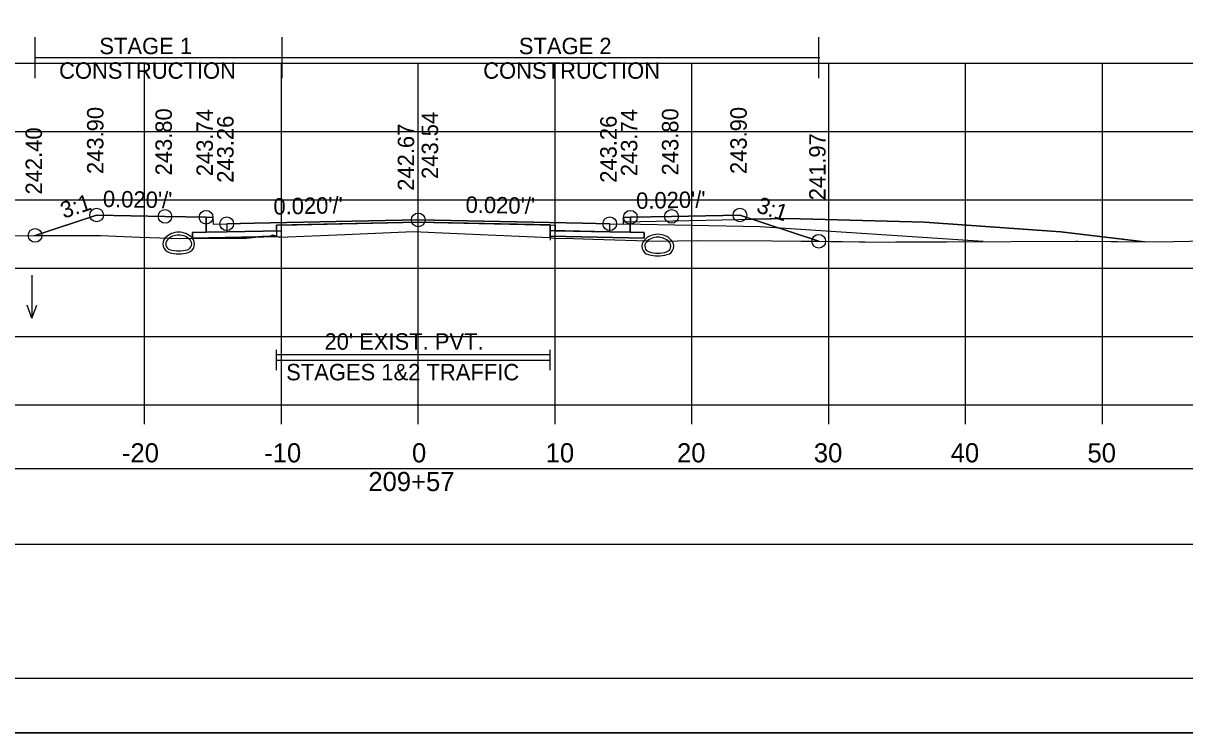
# Model space of a CAD drawing. Extents: x 1369627 to 1374022, y 380035 to 398173.
# Drawn here: x 1372069.7 to 1372154.6, y 381958.8 to 382010.7 of the extents above; entities that cross this region are included whole.
import ezdxf

# ---------------------------------------------------------------- set-up
doc = ezdxf.new("R2010")
doc.units = 0
for name, color, linetype in [('Default', 7, 'Continuous'), ('R_Alt Surface', 7, 'Continuous'), ('R_Axis', 7, 'Continuous'), ('R_Axis Annot', 7, 'Continuous'), ('R_Border', 7, 'Continuous'), ('R_Drive', 7, 'Continuous'), ('R_Exist Surface', 7, 'Continuous'), ('R_Fin Surface', 7, 'Continuous'), ('R_Grid', 7, 'Continuous'), ('R_MOT', 7, 'Continuous'), ('R_No Plot', 7, 'Continuous'), ('R_Water Annot', 7, 'Continuous'), ('R_Xsect Elev', 7, 'Continuous'), ('R_Xsect Slope', 7, 'Continuous'), ('T_Vehicle Path Lt Minor', 7, 'Continuous'), ('T_Vehicle Path Rt', 7, 'Continuous')]:
    doc.layers.add(name, color=color, linetype=linetype)

msp = doc.modelspace()

# ---------------------------------------------------------------- linework, layer by layer
at = {"layer": 'Default'}
for p, q in [((1372088.17, 381985.336), (1372088.17, 381986.836)), ((1372108.17, 381985.336), (1372108.17, 381986.836)), ((1372088.17, 381986.086), (1372108.17, 381986.086))]:
    msp.add_line(p, q, dxfattribs=at)
for points in [[(1372083.02, 381996.536), (1372083.52, 381996.536), (1372083.53, 381996.036), (1372084.53, 381996.056), (1372084.53, 381995.469), (1372083.03, 381995.439)], [(1372113.53, 381996.036), (1372113.54, 381996.536), (1372114.04, 381996.536), (1372114.03, 381995.439), (1372112.53, 381995.469), (1372112.53, 381996.056)], [(1371948.53, 381972.606), (1372248.53, 381972.606), (1372248.53, 381978.128), (1371948.53, 381978.128)]]:
    msp.add_lwpolyline(points, close=True, dxfattribs=at)
at = {"layer": 'R_Alt Surface'}
msp.add_lwpolyline([(1372083.03, 381996.537), (1372083.03, 381995.439), (1372084.53, 381995.469), (1372088.17, 381995.542), (1372088.17, 381995.959), (1372098.53, 381996.166), (1372108.17, 381995.973), (1372108.17, 381995.556), (1372112.53, 381995.469), (1372114.03, 381995.439), (1372114.031, 381996.537)], dxfattribs=at)
for points in [[(1372082.03, 381995.419), (1372083.03, 381995.439), (1372084.53, 381995.469), (1372088.17, 381995.542), (1372088.17, 381995.125), (1372082.03, 381995.003)], [(1372115.03, 381995.419), (1372114.03, 381995.439), (1372112.53, 381995.469), (1372108.17, 381995.556), (1372108.17, 381995.14), (1372115.03, 381995.003)]]:
    msp.add_lwpolyline(points, close=True, dxfattribs=at)
at = {"layer": 'R_Axis'}
for p, q in [((1371948.53, 381982.801), (1372248.53, 381982.801)), ((1372078.53, 381981.401), (1372078.53, 381982.801)), ((1372088.53, 381981.401), (1372088.53, 381982.801)), ((1372098.53, 381981.401), (1372098.53, 381982.801)), ((1372108.53, 381981.401), (1372108.53, 381982.801)), ((1372118.53, 381981.401), (1372118.53, 381982.801)), ((1372128.53, 381981.401), (1372128.53, 381982.801)), ((1372138.53, 381981.401), (1372138.53, 381982.801)), ((1372148.53, 381981.401), (1372148.53, 381982.801))]:
    msp.add_line(p, q, dxfattribs=at)
at = {"layer": 'R_Border'}
msp.add_line((1372256.71, 381962.801), (1371940.53, 381962.801), dxfattribs=at)
at = {"layer": 'R_Drive'}
for points in [[(1372113.53, 381996.036), (1372113.533, 381996.206), (1372125.531, 381996.446)], [(1372125.531, 381996.446), (1372135.527, 381996.186), (1372145.502, 381995.467), (1372151.605, 381994.744)]]:
    msp.add_lwpolyline(points, dxfattribs=at)
for centre, radius, start, end in [((1372081.02, 381994.088), 1.354, 43.64848, 136.35152), ((1372081.02, 381994.088), 1.146, 43.64848, 136.35152), ((1372116.04, 381993.931), 1.354, 43.64848, 136.35152), ((1372080.507, 381994.577), 0.646, 136.35152, 253.95293), ((1372080.507, 381994.577), 0.438, 136.35152, 253.95293), ((1372081.532, 381994.577), 0.438, 286.04707, 43.64848), ((1372081.532, 381994.577), 0.646, 286.04707, 43.64848), ((1372115.527, 381994.42), 0.646, 136.35152, 253.95293), ((1372115.527, 381994.42), 0.438, 136.35152, 253.95293), ((1372116.04, 381993.931), 1.146, 43.64848, 136.35152), ((1372116.552, 381994.42), 0.438, 286.04707, 43.64848), ((1372116.552, 381994.42), 0.646, 286.04707, 43.64848), ((1372081.02, 381996.359), 2.5, 253.95293, 286.04707), ((1372081.02, 381996.359), 2.292, 253.95293, 286.04707), ((1372116.04, 381996.202), 2.5, 253.95293, 286.04707), ((1372116.04, 381996.202), 2.292, 253.95293, 286.04707)]:
    msp.add_arc(centre, radius, start, end, dxfattribs=at)
at = {"layer": 'R_Exist Surface'}
msp.add_lwpolyline([(1372057.766, 381995.056), (1372070.442, 381995.199), (1372075.316, 381995.201), (1372078.169, 381995.085), (1372081.091, 381994.984), (1372082.967, 381995.001), (1372085.721, 381994.968), (1372087.111, 381995.134), (1372087.656, 381995.119), (1372087.879, 381995.217), (1372088.424, 381995.079), (1372093.169, 381995.276), (1372098.17, 381995.487), (1372100.845, 381995.371), (1372108.147, 381995.052), (1372108.284, 381995.039), (1372108.68, 381994.987), (1372109.171, 381995.013), (1372111.299, 381994.938), (1372116.085, 381994.775), (1372118.872, 381994.84), (1372124.387, 381994.813), (1372132.894, 381994.718), (1372133.444, 381994.726), (1372134.919, 381994.73), (1372137.163, 381994.744), (1372146.599, 381994.781), (1372146.673, 381994.781), (1372146.725, 381994.781), (1372152.59, 381994.737), (1372159.589, 381994.884)], dxfattribs=at)
at = {"layer": 'R_Fin Surface'}
msp.add_lwpolyline([(1372070.528, 381995.199), (1372075.02, 381996.696), (1372080.02, 381996.596), (1372083.02, 381996.536), (1372083.52, 381996.536), (1372083.53, 381996.036), (1372084.53, 381996.056), (1372086.53, 381996.096), (1372098.53, 381996.336), (1372110.53, 381996.096), (1372112.53, 381996.056), (1372113.53, 381996.036), (1372113.54, 381996.536), (1372114.04, 381996.536), (1372117.04, 381996.596), (1372122.04, 381996.696), (1372127.803, 381994.775)], dxfattribs=at)
at = {"layer": 'R_Grid'}
for p, q in [((1371948.53, 382007.801), (1372248.53, 382007.801)), ((1372078.53, 381982.801), (1372078.53, 382007.801)), ((1372088.53, 381982.801), (1372088.53, 382007.801)), ((1372098.53, 381982.801), (1372098.53, 382007.801)), ((1372108.53, 381982.801), (1372108.53, 382007.801)), ((1372118.53, 381982.801), (1372118.53, 382007.801)), ((1372128.53, 381982.801), (1372128.53, 382007.801)), ((1372138.53, 381982.801), (1372138.53, 382007.801)), ((1372148.53, 381982.801), (1372148.53, 382007.801)), ((1371948.53, 382002.801), (1372248.53, 382002.801)), ((1371948.53, 381997.801), (1372248.53, 381997.801)), ((1371948.53, 381992.801), (1372248.53, 381992.801)), ((1371948.53, 381987.801), (1372248.53, 381987.801)), ((1371948.53, 381982.801), (1372248.53, 381982.801))]:
    msp.add_line(p, q, dxfattribs=at)
at = {"layer": 'R_MOT'}
for p, q in [((1372070.528, 382006.71), (1372070.528, 382009.71)), ((1372088.581, 382006.71), (1372088.581, 382009.71)), ((1372127.803, 382006.71), (1372127.803, 382009.71)), ((1372070.528, 382008.21), (1372127.89, 382008.21))]:
    msp.add_line(p, q, dxfattribs=at)
at = {"layer": 'R_No Plot'}
for p, q in [((1372123.53, 381995.836), (1372113.53, 381996.036)), ((1372139.822, 381994.761), (1372123.53, 381995.836)), ((1371928.129, 381958.822), (1372261.462, 381958.822))]:
    msp.add_line(p, q, dxfattribs=at)
for points in [[(1371928.122, 382172.155), (1372261.462, 382172.155), (1372261.462, 381958.818), (1371928.122, 381958.818)], [(1372174.45, 382168.261), (1372194.07, 382168.261), (1372194.07, 382158.381), (1372210.182, 382158.381), (1372233.381, 382158.381), (1372233.381, 382125.71), (1372256.589, 382125.71), (1372256.71, 381962.801), (1371940.53, 381962.801), (1371940.53, 382168.261)], [(1372098.53, 381996.336), (1372086.53, 381996.096), (1372084.53, 381996.056), (1372084.53, 381995.469), (1372088.53, 381995.549), (1372088.53, 381995.966), (1372098.53, 381996.166), (1372108.53, 381995.966), (1372108.53, 381995.549), (1372112.53, 381995.469), (1372112.53, 381996.056), (1372110.53, 381996.096)], [(1372088.53, 381995.549), (1372084.53, 381995.469), (1372083.03, 381995.439), (1372082.03, 381995.419), (1372082.03, 381995.002), (1372088.53, 381995.132)], [(1372108.53, 381995.549), (1372112.53, 381995.469), (1372114.03, 381995.439), (1372115.03, 381995.419), (1372115.03, 381995.002), (1372108.53, 381995.132)]]:
    msp.add_lwpolyline(points, close=True, dxfattribs=at)
for points in [[(1372083.02, 381996.536), (1372083.03, 381995.439), (1372084.53, 381995.469), (1372088.53, 381995.549), (1372088.53, 381995.966), (1372098.53, 381996.166), (1372108.53, 381995.966), (1372108.53, 381995.549), (1372112.53, 381995.469), (1372114.03, 381995.439), (1372114.04, 381996.536)], [(1372088.17, 381986.487), (1372108.17, 381986.487)]]:
    msp.add_lwpolyline(points, dxfattribs=at)
for centre in [(1372075.02, 381996.696), (1372080.02, 381996.596), (1372083.02, 381996.536), (1372098.53, 381996.336), (1372114.04, 381996.536), (1372117.04, 381996.596), (1372122.04, 381996.696), (1372084.53, 381996.056), (1372112.53, 381996.056), (1372070.528, 381995.199), (1372127.803, 381994.775)]:
    msp.add_circle(centre, 0.5, dxfattribs=at)
at = {"layer": 'R_Water Annot'}
for p, q in [((1372070.296, 381992.289), (1372070.296, 381989.146)), ((1372070.296, 381989.146), (1372069.945, 381990.108)), ((1372070.296, 381989.146), (1372070.646, 381990.108))]:
    msp.add_line(p, q, dxfattribs=at)
at = {"layer": 'R_Xsect Elev'}
msp.add_line((1372098.53, 381995.471), (1372098.53, 382005.471), dxfattribs=at)
at = {"layer": 'T_Vehicle Path Lt Minor'}
for p, q in [((1372125.531, 381996.446), (1372122.945, 381996.394)), ((1372122.945, 381996.394), (1372127.803, 381994.775))]:
    msp.add_line(p, q, dxfattribs=at)
for points in [[(1372151.605, 381994.744), (1372145.502, 381995.467), (1372135.527, 381996.186), (1372125.531, 381996.446)], [(1372127.803, 381994.775), (1372132.894, 381994.718), (1372133.444, 381994.726), (1372134.919, 381994.73), (1372137.163, 381994.744), (1372146.599, 381994.781), (1372146.673, 381994.781), (1372146.725, 381994.781), (1372151.605, 381994.744)]]:
    msp.add_lwpolyline(points, dxfattribs=at)
at = {"layer": 'T_Vehicle Path Rt'}
for p, q in [((1372083.03, 381995.439), (1372083.02, 381996.536)), ((1372114.04, 381996.536), (1372114.03, 381995.439)), ((1372086.811, 381995.098), (1372082.03, 381995.003)), ((1372086.811, 381995.098), (1372087.656, 381995.115)), ((1372087.656, 381995.115), (1372088.17, 381995.125)), ((1372088.17, 381995.542), (1372088.17, 381995.144)), ((1372088.17, 381995.125), (1372088.17, 381995.144)), ((1372108.17, 381995.14), (1372108.17, 381995.556)), ((1372108.17, 381995.14), (1372108.17, 381994.86)), ((1372108.17, 381995.14), (1372108.17, 381995.05)), ((1372108.17, 381995.05), (1372108.17, 381995.14))]:
    msp.add_line(p, q, dxfattribs=at)
for points in [[(1372083.02, 381996.536), (1372080.02, 381996.596), (1372075.02, 381996.696), (1372070.528, 381995.199)], [(1372108.17, 381995.556), (1372108.17, 381995.973), (1372098.53, 381996.166), (1372088.17, 381995.959), (1372088.17, 381995.542)], [(1372127.803, 381994.775), (1372122.04, 381996.696), (1372117.04, 381996.596), (1372114.04, 381996.536)], [(1372070.528, 381995.199), (1372075.316, 381995.201), (1372078.169, 381995.085), (1372081.091, 381994.984), (1372082.03, 381994.992), (1372082.967, 381995.001), (1372085.721, 381994.968), (1372086.811, 381995.098)], [(1372082.03, 381995.003), (1372082.03, 381995.419), (1372083.03, 381995.439)], [(1372087.656, 381995.119), (1372087.111, 381995.134), (1372086.811, 381995.098)], [(1372088.17, 381995.144), (1372087.879, 381995.217), (1372087.656, 381995.119)], [(1372087.656, 381995.119), (1372087.656, 381995.115)], [(1372087.656, 381995.115), (1372087.656, 381995.119)], [(1372088.17, 381995.144), (1372088.424, 381995.079), (1372093.169, 381995.276), (1372098.17, 381995.487), (1372100.845, 381995.371), (1372108.147, 381995.052), (1372108.17, 381995.05)], [(1372114.03, 381995.439), (1372115.03, 381995.419), (1372115.03, 381995.003), (1372108.17, 381995.14)], [(1372108.17, 381995.05), (1372108.284, 381995.039), (1372108.68, 381994.987), (1372109.171, 381995.013), (1372111.299, 381994.938), (1372116.085, 381994.775), (1372118.872, 381994.84), (1372124.387, 381994.813), (1372127.803, 381994.775)]]:
    msp.add_lwpolyline(points, dxfattribs=at)

# ---------------------------------------------------------------- texts
at = {"layer": 'R_Axis Annot'}
for s, height, p in [("20' EXIST. PVT.", 1.2, (1372091.673, 381986.843)), ('STAGES 1&2 TRAFFIC', 1.2, (1372088.877, 381984.604)), ('-20', 1.4, (1372076.871, 381978.601)), ('-10', 1.4, (1372087.268, 381978.601)), ('0', 1.4, (1372098.072, 381978.601)), ('10', 1.4, (1372107.841, 381978.601)), ('20', 1.4, (1372117.444, 381978.601)), ('30', 1.4, (1372127.444, 381978.601)), ('40', 1.4, (1372137.444, 381978.601)), ('50', 1.4, (1372147.444, 381978.601)), ('209+57', 1.4, (1372094.881, 381976.501))]:
    msp.add_text(s, height=height, dxfattribs=at).set_placement(p)
at = {"layer": 'R_MOT'}
for s, p in [('STAGE 1', (1372075.22, 382008.466)), ('STAGE 2', (1372105.881, 382008.466)), ('CONSTRUCTION', (1372072.277, 382006.666)), ('CONSTRUCTION', (1372103.278, 382006.666))]:
    msp.add_text(s, height=1.2, dxfattribs=at).set_placement(p)
at = {"layer": 'R_Xsect Elev'}
for s, p in [('243.90', (1372075.52, 381999.696)), ('243.80', (1372080.52, 381999.596)), ('243.80', (1372117.54, 381999.596)), ('243.90', (1372122.54, 381999.696)), ('243.74', (1372083.52, 381999.536)), ('243.26', (1372085.03, 381999.056)), ('243.54', (1372099.981, 381999.336)), ('243.26', (1372113.03, 381999.056)), ('243.74', (1372114.54, 381999.536)), ('242.40', (1372071.028, 381998.199)), ('242.67', (1372098.23, 381998.471)), ('241.97', (1372128.303, 381997.775))]:
    msp.add_text(s, height=1.2, rotation=90, dxfattribs=at).set_placement(p)
at = {"layer": 'R_Xsect Slope'}
for s, rotation, p in [("0.020'/'", 358.85424, (1372075.47, 381997.287)), ("0.020'/'", 1.14576, (1372114.466, 381997.144)), ('3:1', 18.43323, (1372072.616, 381996.422)), ("0.020'/'", 1.14576, (1372087.956, 381996.724)), ("0.020'/'", 358.85424, (1372101.98, 381996.867)), ('3:1', 341.56677, (1372123.175, 381996.924))]:
    msp.add_text(s, height=1.2, rotation=rotation, dxfattribs=at).set_placement(p)

doc.saveas('drawing.dxf')
